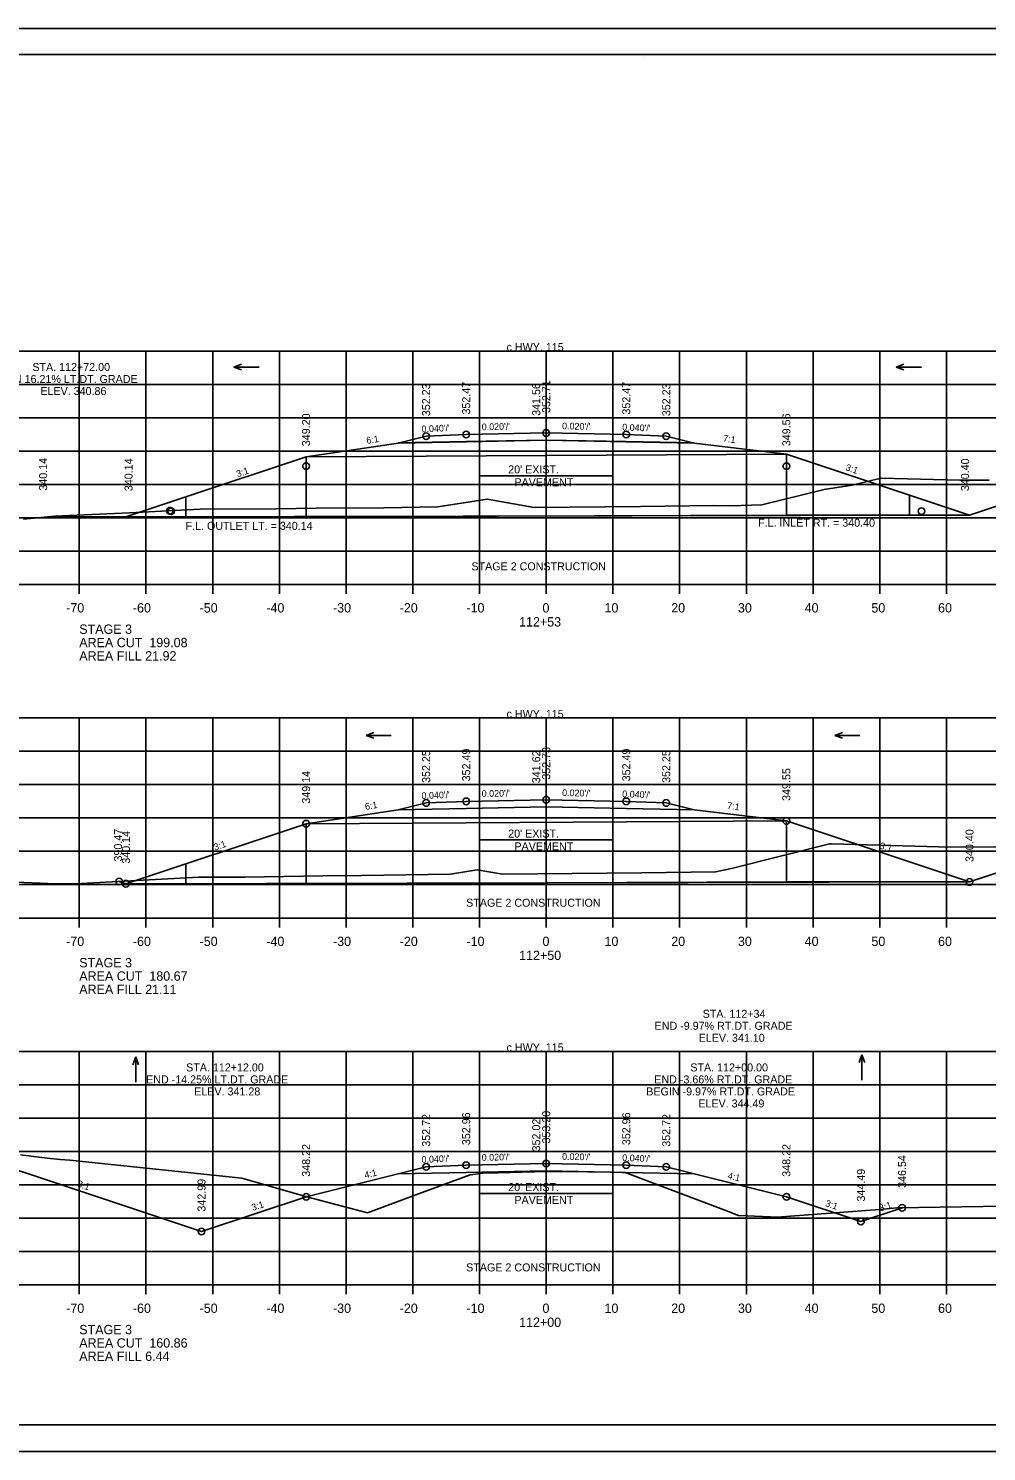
# Model space of a CAD drawing. Extents: x 1630712 to 1632516, y 782146 to 785403.
# Drawn here: x 1632255.3 to 1632399, y 784550 to 784763.3 of the extents above; entities that cross this region are included whole.
import ezdxf

# ---------------------------------------------------------------- set-up
doc = ezdxf.new("R2010")
doc.units = 0
for name, color, linetype in [('Default', 7, 'Continuous'), ('Notes', 7, 'Continuous'), ('R_Alt Surface', 7, 'Continuous'), ('R_Axis', 7, 'Continuous'), ('R_Axis Annot', 7, 'Continuous'), ('R_Border', 7, 'Continuous'), ('R_Culvert', 7, 'Continuous'), ('R_Detour Surface', 7, 'Continuous'), ('R_Exist Surface', 7, 'Continuous'), ('R_Fin Surface', 7, 'Continuous'), ('R_Grid', 7, 'Continuous'), ('R_No Plot', 7, 'Continuous'), ('R_Water Annot', 7, 'Continuous'), ('R_Xsect Elev', 7, 'Continuous'), ('R_Xsect Slope', 7, 'Continuous')]:
    doc.layers.add(name, color=color, linetype=linetype)

msp = doc.modelspace()

# ---------------------------------------------------------------- linework, layer by layer
at = {"layer": 'Default'}
msp.add_line((1632396.41, 784635.37), (1632411.85, 784640.51), dxfattribs=at)
at = {"layer": 'Notes'}
for p, q in [((1632322.96, 784694.56), (1632322.96, 784697.96)), ((1632322.96, 784696.26), (1632342.96, 784696.26)), ((1632342.96, 784694.56), (1632342.96, 784697.96)), ((1632322.96, 784639.97), (1632322.96, 784643.37)), ((1632342.96, 784639.97), (1632342.96, 784643.37)), ((1632322.96, 784641.67), (1632342.96, 784641.67)), ((1632322.96, 784586.97), (1632322.96, 784590.37)), ((1632342.96, 784586.97), (1632342.96, 784590.37)), ((1632322.96, 784588.67), (1632342.96, 784588.67))]:
    msp.add_line(p, q, dxfattribs=at)
at = {"layer": 'R_Alt Surface'}
for points in [[(1632310.78, 784701.18), (1632320.96, 784701.38), (1632332.96, 784701.62), (1632344.96, 784701.38), (1632355.15, 784701.18)], [(1632310.78, 784701.16), (1632320.96, 784701.36), (1632332.96, 784701.6), (1632344.96, 784701.36), (1632355.15, 784701.16)], [(1632310.78, 784646.18), (1632320.96, 784646.38), (1632332.96, 784646.62), (1632344.96, 784646.38), (1632355.15, 784646.18)], [(1632310.78, 784591.64), (1632320.96, 784591.84), (1632332.96, 784592.08), (1632344.96, 784591.84), (1632355.15, 784591.64)]]:
    msp.add_lwpolyline(points, dxfattribs=at)
at = {"layer": 'R_Axis'}
for p, q in [((1632212.96, 784679.97), (1632492.96, 784679.97)), ((1632262.96, 784678.57), (1632262.96, 784679.97)), ((1632272.96, 784678.57), (1632272.96, 784679.97)), ((1632282.96, 784678.57), (1632282.96, 784679.97)), ((1632292.96, 784678.57), (1632292.96, 784679.97)), ((1632302.96, 784678.57), (1632302.96, 784679.97)), ((1632312.96, 784678.57), (1632312.96, 784679.97)), ((1632322.96, 784678.57), (1632322.96, 784679.97)), ((1632332.96, 784678.57), (1632332.96, 784679.97)), ((1632342.96, 784678.57), (1632342.96, 784679.97)), ((1632352.96, 784678.57), (1632352.96, 784679.97)), ((1632362.96, 784678.57), (1632362.96, 784679.97)), ((1632372.96, 784678.57), (1632372.96, 784679.97)), ((1632382.96, 784678.57), (1632382.96, 784679.97)), ((1632392.96, 784678.57), (1632392.96, 784679.97)), ((1632212.96, 784629.97), (1632492.96, 784629.97)), ((1632262.96, 784628.57), (1632262.96, 784629.97)), ((1632272.96, 784628.57), (1632272.96, 784629.97)), ((1632282.96, 784628.57), (1632282.96, 784629.97)), ((1632292.96, 784628.57), (1632292.96, 784629.97)), ((1632302.96, 784628.57), (1632302.96, 784629.97)), ((1632312.96, 784628.57), (1632312.96, 784629.97)), ((1632322.96, 784628.57), (1632322.96, 784629.97)), ((1632332.96, 784628.57), (1632332.96, 784629.97)), ((1632342.96, 784628.57), (1632342.96, 784629.97)), ((1632352.96, 784628.57), (1632352.96, 784629.97)), ((1632362.96, 784628.57), (1632362.96, 784629.97)), ((1632372.96, 784628.57), (1632372.96, 784629.97)), ((1632382.96, 784628.57), (1632382.96, 784629.97)), ((1632392.96, 784628.57), (1632392.96, 784629.97)), ((1632212.96, 784574.97), (1632492.96, 784574.97)), ((1632262.96, 784573.57), (1632262.96, 784574.97)), ((1632272.96, 784573.57), (1632272.96, 784574.97)), ((1632282.96, 784573.57), (1632282.96, 784574.97)), ((1632292.96, 784573.57), (1632292.96, 784574.97)), ((1632302.96, 784573.57), (1632302.96, 784574.97)), ((1632312.96, 784573.57), (1632312.96, 784574.97)), ((1632322.96, 784573.57), (1632322.96, 784574.97)), ((1632332.96, 784573.57), (1632332.96, 784574.97)), ((1632342.96, 784573.57), (1632342.96, 784574.97)), ((1632352.96, 784573.57), (1632352.96, 784574.97)), ((1632362.96, 784573.57), (1632362.96, 784574.97)), ((1632372.96, 784573.57), (1632372.96, 784574.97)), ((1632382.96, 784573.57), (1632382.96, 784574.97)), ((1632392.96, 784573.57), (1632392.96, 784574.97))]:
    msp.add_line(p, q, dxfattribs=at)
at = {"layer": 'R_Border'}
for p, q in [((1632194.96, 784759.43), (1632511.14, 784759.43)), ((1632347.48, 784759.17), (1632347.48, 784759.17)), ((1632347.48, 784759.17), (1632347.48, 784759.17)), ((1632511.14, 784553.97), (1632194.96, 784553.97))]:
    msp.add_line(p, q, dxfattribs=at)
at = {"layer": 'R_Culvert'}
for p, q in [((1632368.96, 784699.52), (1632296.96, 784699.11)), ((1632368.96, 784690.37), (1632296.96, 784690.11)), ((1632368.96, 784644.52), (1632296.96, 784644.11)), ((1632368.96, 784635.37), (1632296.96, 784635.11))]:
    msp.add_line(p, q, dxfattribs=at)
for points in [[(1632296.96, 784699.11), (1632296.96, 784690.11)], [(1632368.96, 784699.52), (1632368.96, 784690.37)], [(1632278.96, 784690.11), (1632278.96, 784693.11)], [(1632387.41, 784693.37), (1632387.41, 784690.37)], [(1632258.22, 784690.11), (1632296.96, 784690.11)], [(1632368.96, 784690.37), (1632396.41, 784690.37)], [(1632296.96, 784644.11), (1632296.96, 784635.11)], [(1632368.96, 784644.52), (1632368.96, 784635.37)], [(1632278.96, 784635.11), (1632278.96, 784638.11)], [(1632269.96, 784635.11), (1632296.96, 784635.11)], [(1632368.96, 784635.37), (1632396.41, 784635.37)]]:
    msp.add_lwpolyline(points, dxfattribs=at)
at = {"layer": 'R_Detour Surface'}
for p, q in [((1632269.96, 784690.11), (1632396.41, 784690.37)), ((1632269.96, 784635.11), (1632396.41, 784635.37))]:
    msp.add_line(p, q, dxfattribs=at)
at = {"layer": 'R_Exist Surface'}
for points in [[(1632254.61, 784689.78), (1632259.24, 784690.2), (1632270.47, 784690.71), (1632281.07, 784691.27), (1632292.47, 784691.3), (1632298.5, 784691.4), (1632308.6, 784691.45), (1632316.72, 784691.59), (1632324.13, 784692.76), (1632331.17, 784691.52), (1632347.11, 784691.68), (1632358.06, 784691.82), (1632360.65, 784691.76), (1632365.28, 784691.9), (1632374.64, 784694.21), (1632378.81, 784694.84), (1632383.17, 784695.93), (1632394.95, 784695.59), (1632399.38, 784695.62)], [(1632244.82, 784635.71), (1632259.53, 784635.1), (1632263.27, 784635.14), (1632280.91, 784636.07), (1632287.84, 784636.09), (1632299.45, 784636.29), (1632305.27, 784636.32), (1632318.61, 784636.56), (1632322.6, 784637.19), (1632326.39, 784636.52), (1632347.23, 784636.74), (1632358.36, 784636.87), (1632360.71, 784637.4), (1632375.45, 784641.09), (1632375.48, 784641.09), (1632375.57, 784641.09), (1632375.7, 784641.09), (1632393.57, 784640.58), (1632400.37, 784640.63)], [(1632254.16, 784594.48), (1632258.14, 784593.99), (1632260.09, 784593.78), (1632261.57, 784593.69), (1632287.31, 784590.98), (1632297.09, 784588.15), (1632306.16, 784585.75), (1632313.43, 784588.47), (1632321.54, 784591.49), (1632322.78, 784591.63), (1632323.44, 784591.7), (1632325.76, 784591.76), (1632333.01, 784591.99), (1632335.61, 784591.97), (1632342.73, 784591.89), (1632344.38, 784591.84), (1632344.81, 784591.83), (1632360.15, 784586), (1632361.39, 784585.53), (1632361.76, 784585.38), (1632366.59, 784585.17), (1632367.6, 784585.13), (1632382.94, 784586.29), (1632385.52, 784586.5), (1632408.13, 784586.85)]]:
    msp.add_lwpolyline(points, dxfattribs=at)
at = {"layer": 'R_Fin Surface'}
for points in [[(1632269.96, 784690.11), (1632269.96, 784690.11), (1632278.96, 784693.11), (1632296.96, 784699.11), (1632310.78, 784701.16), (1632314.96, 784702.2), (1632320.96, 784702.44), (1632332.96, 784702.68), (1632344.96, 784702.44), (1632350.96, 784702.2), (1632355.15, 784701.16), (1632368.96, 784699.52), (1632396.41, 784690.37)], [(1632396.41, 784690.37), (1632399.41, 784691.37), (1632409.63, 784694.78)], [(1632268.96, 784635.44), (1632269.96, 784635.11), (1632296.96, 784644.11), (1632310.78, 784646.18), (1632314.96, 784647.22), (1632320.96, 784647.46), (1632332.96, 784647.7), (1632344.96, 784647.46), (1632350.96, 784647.22), (1632355.15, 784646.18), (1632368.96, 784644.52), (1632396.41, 784635.37), (1632411.85, 784640.51)], [(1632243.98, 784595.4), (1632251.88, 784592.76), (1632252.83, 784592.44), (1632253.65, 784592.17), (1632253.86, 784592.1), (1632254.09, 784592.02), (1632254.29, 784591.96), (1632254.44, 784591.91), (1632263.73, 784588.81), (1632281.29, 784582.96), (1632296.96, 784588.18), (1632310.78, 784591.64), (1632314.96, 784592.68), (1632320.96, 784592.92), (1632332.96, 784593.16), (1632344.96, 784592.92), (1632350.96, 784592.68), (1632355.15, 784591.64), (1632368.96, 784588.18), (1632380.14, 784584.46), (1632386.3, 784586.51)]]:
    msp.add_lwpolyline(points, dxfattribs=at)
at = {"layer": 'R_Grid'}
for p, q in [((1632212.96, 784714.97), (1632492.96, 784714.97)), ((1632262.96, 784679.97), (1632262.96, 784714.97)), ((1632272.96, 784679.97), (1632272.96, 784714.97)), ((1632282.96, 784679.97), (1632282.96, 784714.97)), ((1632292.96, 784679.97), (1632292.96, 784714.97)), ((1632302.96, 784679.97), (1632302.96, 784714.97)), ((1632312.96, 784679.97), (1632312.96, 784714.97)), ((1632322.96, 784679.97), (1632322.96, 784714.97)), ((1632332.96, 784679.97), (1632332.96, 784714.97)), ((1632342.96, 784679.97), (1632342.96, 784714.97)), ((1632352.96, 784679.97), (1632352.96, 784714.97)), ((1632362.96, 784679.97), (1632362.96, 784714.97)), ((1632372.96, 784679.97), (1632372.96, 784714.97)), ((1632382.96, 784679.97), (1632382.96, 784714.97)), ((1632392.96, 784679.97), (1632392.96, 784714.97)), ((1632212.96, 784709.97), (1632492.96, 784709.97)), ((1632212.96, 784704.97), (1632492.96, 784704.97)), ((1632212.96, 784699.97), (1632492.96, 784699.97)), ((1632212.96, 784694.97), (1632492.96, 784694.97)), ((1632212.96, 784689.97), (1632492.96, 784689.97)), ((1632212.96, 784684.97), (1632492.96, 784684.97)), ((1632212.96, 784679.97), (1632492.96, 784679.97)), ((1632212.96, 784659.97), (1632492.96, 784659.97)), ((1632262.96, 784629.97), (1632262.96, 784659.97)), ((1632272.96, 784629.97), (1632272.96, 784659.97)), ((1632282.96, 784629.97), (1632282.96, 784659.97)), ((1632292.96, 784629.97), (1632292.96, 784659.97)), ((1632302.96, 784629.97), (1632302.96, 784659.97)), ((1632312.96, 784629.97), (1632312.96, 784659.97)), ((1632322.96, 784629.97), (1632322.96, 784659.97)), ((1632332.96, 784629.97), (1632332.96, 784659.97)), ((1632342.96, 784629.97), (1632342.96, 784659.97)), ((1632352.96, 784629.97), (1632352.96, 784659.97)), ((1632362.96, 784629.97), (1632362.96, 784659.97)), ((1632372.96, 784629.97), (1632372.96, 784659.97)), ((1632382.96, 784629.97), (1632382.96, 784659.97)), ((1632392.96, 784629.97), (1632392.96, 784659.97)), ((1632212.96, 784654.97), (1632492.96, 784654.97)), ((1632212.96, 784649.97), (1632492.96, 784649.97)), ((1632212.96, 784644.97), (1632492.96, 784644.97)), ((1632212.96, 784639.97), (1632492.96, 784639.97)), ((1632212.96, 784634.97), (1632492.96, 784634.97)), ((1632212.96, 784629.97), (1632492.96, 784629.97)), ((1632212.96, 784609.97), (1632492.96, 784609.97)), ((1632262.96, 784574.97), (1632262.96, 784609.97)), ((1632272.96, 784574.97), (1632272.96, 784609.97)), ((1632282.96, 784574.97), (1632282.96, 784609.97)), ((1632292.96, 784574.97), (1632292.96, 784609.97)), ((1632302.96, 784574.97), (1632302.96, 784609.97)), ((1632312.96, 784574.97), (1632312.96, 784609.97)), ((1632322.96, 784574.97), (1632322.96, 784609.97)), ((1632332.96, 784574.97), (1632332.96, 784609.97)), ((1632342.96, 784574.97), (1632342.96, 784609.97)), ((1632352.96, 784574.97), (1632352.96, 784609.97)), ((1632362.96, 784574.97), (1632362.96, 784609.97)), ((1632372.96, 784574.97), (1632372.96, 784609.97)), ((1632382.96, 784574.97), (1632382.96, 784609.97)), ((1632392.96, 784574.97), (1632392.96, 784609.97)), ((1632212.96, 784604.97), (1632492.96, 784604.97)), ((1632212.96, 784599.97), (1632492.96, 784599.97)), ((1632212.96, 784594.97), (1632492.96, 784594.97)), ((1632212.96, 784589.97), (1632492.96, 784589.97)), ((1632212.96, 784584.97), (1632492.96, 784584.97)), ((1632212.96, 784579.97), (1632492.96, 784579.97)), ((1632212.96, 784574.97), (1632492.96, 784574.97))]:
    msp.add_line(p, q, dxfattribs=at)
at = {"layer": 'R_No Plot'}
for p, q in [((1632182.56, 784763.32), (1632515.9, 784763.32)), ((1632182.56, 784549.99), (1632515.9, 784549.99))]:
    msp.add_line(p, q, dxfattribs=at)
msp.add_lwpolyline([(1632182.56, 784763.32), (1632515.9, 784763.32), (1632515.9, 784549.99), (1632182.56, 784549.99)], close=True, dxfattribs=at)
for centre in [(1632314.96, 784702.2), (1632320.96, 784702.44), (1632332.96, 784702.68), (1632344.96, 784702.44), (1632350.96, 784702.2), (1632296.96, 784697.7), (1632368.96, 784697.7), (1632276.54, 784691.03), (1632276.54, 784691.03), (1632276.74, 784690.96), (1632389.21, 784690.96), (1632314.96, 784647.22), (1632320.96, 784647.46), (1632332.96, 784647.7), (1632344.96, 784647.46), (1632350.96, 784647.22), (1632296.96, 784644.11), (1632368.96, 784644.52), (1632268.96, 784635.44), (1632269.96, 784635.11), (1632396.41, 784635.37), (1632314.96, 784592.68), (1632320.96, 784592.92), (1632332.96, 784593.16), (1632344.96, 784592.92), (1632350.96, 784592.68), (1632296.96, 784588.18), (1632368.96, 784588.18), (1632386.3, 784586.51), (1632281.29, 784582.96), (1632380.14, 784584.46)]:
    msp.add_circle(centre, 0.5, dxfattribs=at)
at = {"layer": 'R_Water Annot'}
for p, q in [((1632286.14, 784712.56), (1632287.29, 784712.98)), ((1632289.91, 784712.56), (1632286.14, 784712.56)), ((1632286.14, 784712.56), (1632287.29, 784712.14)), ((1632385.44, 784712.56), (1632386.59, 784712.98)), ((1632389.21, 784712.56), (1632385.44, 784712.56)), ((1632385.44, 784712.56), (1632386.59, 784712.14)), ((1632305.95, 784657.35), (1632307.1, 784657.77)), ((1632309.72, 784657.35), (1632305.95, 784657.35)), ((1632305.95, 784657.35), (1632307.1, 784656.93)), ((1632376.2, 784657.35), (1632377.36, 784657.77)), ((1632379.97, 784657.35), (1632376.2, 784657.35)), ((1632376.2, 784657.35), (1632377.36, 784656.93)), ((1632271.42, 784609.14), (1632271, 784607.98)), ((1632271.42, 784605.36), (1632271.42, 784609.14)), ((1632271.42, 784609.14), (1632271.84, 784607.98)), ((1632380.29, 784609.45), (1632379.87, 784608.3)), ((1632380.29, 784605.68), (1632380.29, 784609.45)), ((1632380.29, 784609.45), (1632380.71, 784608.3))]:
    msp.add_line(p, q, dxfattribs=at)

# ---------------------------------------------------------------- texts
at = {"layer": 'Notes'}
for s, p in [('c HWY. 115', (1632327.02, 784714.97)), ('BEGIN 16.21% LT.DT. GRADE', (1632249.33, 784710.17)), ('STA. 112+72.00', (1632255.93, 784711.97)), ('ELEV. 340.86', (1632257.13, 784708.37)), ("20' EXIST.", (1632327.26, 784696.62)), ('PAVEMENT', (1632328.19, 784694.7)), ('F.L. INLET RT. = 340.40', (1632364.72, 784688.63)), ('F.L. OUTLET LT. = 340.14', (1632278.9, 784688.16)), ('STAGE 2 CONSTRUCTION', (1632321.75, 784682.09)), ('c HWY. 115', (1632327.02, 784659.97)), ("20' EXIST.", (1632327.26, 784642.03)), ('PAVEMENT', (1632328.19, 784640.11)), ('STAGE 2 CONSTRUCTION', (1632320.96, 784631.66)), ('STA. 112+34', (1632356.41, 784615.01)), ('END -9.97% RT.DT. GRADE', (1632349.21, 784613.21)), ('c HWY. 115', (1632327.02, 784609.97)), ('ELEV. 341.10', (1632355.81, 784611.41)), ('STA. 112+12.00', (1632278.98, 784606.97)), ('STA. 112+00.00', (1632354.56, 784606.97)), ('END -14.25% LT.DT. GRADE', (1632272.98, 784605.17)), ('ELEV. 341.28', (1632280.19, 784603.37)), ('BEGIN -9.97% RT.DT. GRADE', (1632347.96, 784603.37)), ('END -3.66% RT.DT. GRADE', (1632349.16, 784605.17)), ('ELEV. 344.49', (1632355.76, 784601.57)), ("20' EXIST.", (1632327.26, 784589.03)), ('PAVEMENT', (1632328.19, 784587.11)), ('STAGE 2 CONSTRUCTION', (1632320.96, 784576.99))]:
    msp.add_text(s, height=1.2, dxfattribs=at).set_placement(p)
msp.add_text('3:1', height=1, rotation=341.5506, dxfattribs=at).set_placement((1632262.59, 784589.72))
at = {"layer": 'R_Axis Annot'}
for s, p in [('-70', (1632261, 784675.77)), ('-60', (1632271, 784675.77)), ('-50', (1632281, 784675.77)), ('-40', (1632291, 784675.77)), ('-30', (1632301, 784675.77)), ('-20', (1632311, 784675.77)), ('-10', (1632321, 784675.77)), ('0', (1632332.4, 784675.77)), ('10', (1632341.7, 784675.77)), ('20', (1632351.7, 784675.77)), ('30', (1632361.7, 784675.77)), ('40', (1632371.7, 784675.77)), ('50', (1632381.7, 784675.77)), ('60', (1632391.7, 784675.77)), ('112+53', (1632328.89, 784673.67)), ('STAGE 3', (1632262.96, 784672.57)), ('AREA CUT  199.08', (1632262.96, 784670.57)), ('AREA FILL 21.92', (1632262.96, 784668.57)), ('-70', (1632261, 784625.77)), ('-60', (1632271, 784625.77)), ('-50', (1632281, 784625.77)), ('-40', (1632291, 784625.77)), ('-30', (1632301, 784625.77)), ('-20', (1632311, 784625.77)), ('-10', (1632321, 784625.77)), ('0', (1632332.4, 784625.77)), ('10', (1632341.7, 784625.77)), ('20', (1632351.7, 784625.77)), ('30', (1632361.7, 784625.77)), ('40', (1632371.7, 784625.77)), ('50', (1632381.7, 784625.77)), ('60', (1632391.7, 784625.77)), ('STAGE 3', (1632262.96, 784622.57)), ('112+50', (1632328.9, 784623.67)), ('AREA CUT  180.67', (1632262.96, 784620.57)), ('AREA FILL 21.11', (1632262.96, 784618.57)), ('-70', (1632261, 784570.77)), ('-60', (1632271, 784570.77)), ('-50', (1632281, 784570.77)), ('-40', (1632291, 784570.77)), ('-30', (1632301, 784570.77)), ('-20', (1632311, 784570.77)), ('-10', (1632321, 784570.77)), ('0', (1632332.4, 784570.77)), ('10', (1632341.7, 784570.77)), ('20', (1632351.7, 784570.77)), ('30', (1632361.7, 784570.77)), ('40', (1632371.7, 784570.77)), ('50', (1632381.7, 784570.77)), ('60', (1632391.7, 784570.77)), ('STAGE 3', (1632262.96, 784567.57)), ('112+00', (1632328.9, 784568.67)), ('AREA CUT  160.86', (1632262.96, 784565.57)), ('AREA FILL 6.44', (1632262.96, 784563.57))]:
    msp.add_text(s, height=1.4, dxfattribs=at).set_placement(p)
at = {"layer": 'R_Xsect Elev'}
for s, p in [('352.23', (1632315.56, 784705.2)), ('352.47', (1632321.56, 784705.44)), ('341.56', (1632332.06, 784705.25)), ('352.71', (1632333.56, 784705.68)), ('352.47', (1632345.56, 784705.44)), ('352.23', (1632351.56, 784705.2)), ('349.20', (1632297.56, 784700.7)), ('349.56', (1632369.56, 784700.7)), ('340.14', (1632258.14, 784694.03)), ('340.14', (1632270.95, 784693.96)), ('340.40', (1632396.34, 784693.96)), ('352.25', (1632315.56, 784650.22)), ('352.49', (1632321.56, 784650.46)), ('341.62', (1632332.06, 784650.18)), ('352.73', (1632333.56, 784650.7)), ('352.49', (1632345.56, 784650.46)), ('352.25', (1632351.56, 784650.22)), ('349.14', (1632297.56, 784647.11)), ('349.55', (1632369.56, 784647.52)), ('390.47', (1632269.37, 784638.44)), ('340.14', (1632270.56, 784638.11)), ('340.40', (1632397.01, 784638.37)), ('352.72', (1632315.56, 784595.68)), ('352.96', (1632321.56, 784595.92)), ('353.20', (1632333.56, 784596.16)), ('352.96', (1632345.56, 784595.92)), ('352.72', (1632351.56, 784595.68)), ('352.02', (1632332.06, 784594.98)), ('348.22', (1632297.56, 784591.18)), ('348.22', (1632369.56, 784591.18)), ('346.54', (1632386.9, 784589.51)), ('344.49', (1632380.74, 784587.46)), ('342.99', (1632281.89, 784585.96))]:
    msp.add_text(s, height=1.2, rotation=90, dxfattribs=at).set_placement(p)
at = {"layer": 'R_Xsect Slope'}
for s, rotation, p in [("0.040'/'", 2.2906, (1632314.29, 784702.78)), ("0.020'/'", 1.1458, (1632323.3, 784703.09)), ("0.020'/'", 358.8542, (1632335.33, 784703.24)), ("0.040'/'", 357.7094, (1632344.34, 784703.07)), ('6:1', 9.0362, (1632306.08, 784701.05)), ('7:1', 350.9638, (1632359.42, 784701.43)), ('3:1', 18.4349, (1632286.7, 784696.04)), ('3:1', 341.5651, (1632377.75, 784697.11)), ('6:1', 9.8161, (1632305.88, 784646.16)), ("0.040'/'", 2.2906, (1632314.29, 784647.8)), ("0.020'/'", 1.1458, (1632323.3, 784648.11)), ("0.020'/'", 358.8542, (1632335.33, 784648.26)), ("0.040'/'", 357.7094, (1632344.34, 784648.09)), ('7:1', 351.4543, (1632360.04, 784646.37)), ('3:1', 18.4349, (1632283.31, 784640.08)), ('3:1', 341.5651, (1632382.85, 784640.42)), ("0.040'/'", 2.2906, (1632314.29, 784593.26)), ("0.020'/'", 1.1458, (1632323.3, 784593.57)), ("0.020'/'", 358.8542, (1632335.33, 784593.72)), ("0.040'/'", 357.7094, (1632344.34, 784593.55)), ('4:1', 14.0362, (1632305.84, 784590.92)), ('4:1', 345.9638, (1632360.09, 784590.92)), ('3:1', 18.4349, (1632288.97, 784586.05)), ('3:1', 341.5651, (1632374.71, 784586.8)), ('3:1', 18.4349, (1632383.06, 784585.96))]:
    msp.add_text(s, height=1, rotation=rotation, dxfattribs=at).set_placement(p)

doc.saveas('drawing.dxf')
